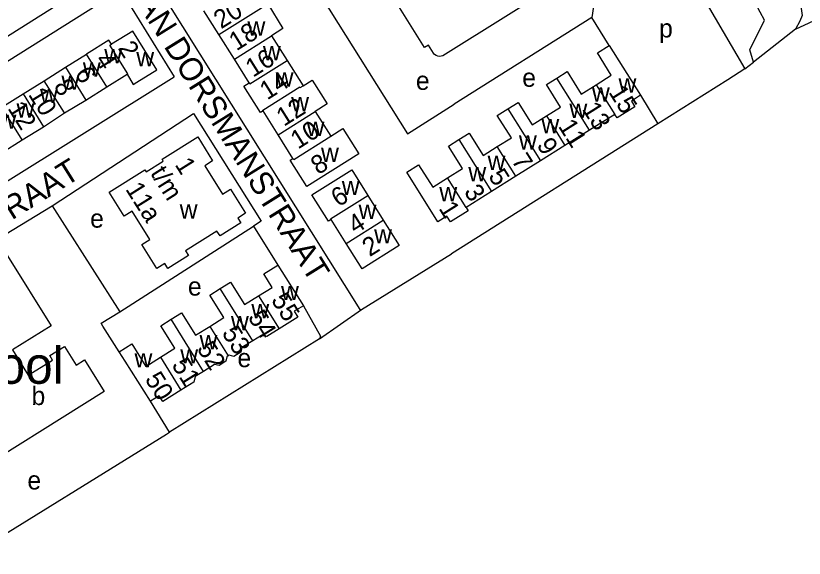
# Model space of a CAD drawing. Extents: x 158848 to 160613, y 385889 to 387762.
# Drawn here: x 159841.7 to 160012.4, y 385996.6 to 386114 of the extents above; entities that cross this region are included whole.
import ezdxf

# ---------------------------------------------------------------- set-up
doc = ezdxf.new("R2010")
doc.units = 0
for name, color, linetype in [('BLT_Basislijn', 7, 'Continuous'), ('BLT_Bebouwing', 7, 'Continuous'), ('BLT_Bebouwing_beschrifting', 7, 'Continuous'), ('BLT_Centroide', 7, 'Continuous'), ('BLT_Huisnummer', 7, 'Continuous'), ('BLT_Huisnummer_ tussenligend', 7, 'Continuous'), ('BLT_Huisnummer_reeks', 7, 'Continuous'), ('BLT_Onderverdeling_panden', 7, 'Continuous'), ('BLT_Straatnaam', 7, 'Continuous'), ('BLT_Vlakafsluiter', 7, 'Continuous')]:
    doc.layers.add(name, color=color, linetype=linetype)

msp = doc.modelspace()

# ---------------------------------------------------------------- linework, layer by layer
at = {"layer": 'BLT_Basislijn'}
for p, q in [((159895.1, 386138.5), (159926.53, 386088.5)), ((159832.6, 386099.65), (159864.36, 386119.63)), ((159864.36, 386119.63), (159876.02, 386100.84)), ((159760.3, 386059.31), (159851.79, 386117.16)), ((159966.41, 386113.66), (159936.62, 386094.87)), ((160010.47, 386111.11), (160001.42, 386104.03)), ((159999.52, 386102.54), (160001.42, 386104.03)), ((159999.52, 386102.54), (159995.82, 386100.15)), ((159762, 386029.78), (159876.02, 386100.84)), ((159995.82, 386100.15), (159980.72, 386090.65)), ((159976.9, 386096.82), (159980.72, 386090.65)), ((159926.53, 386088.5), (159936.62, 386094.87)), ((159849.59, 386072.9), (159880.17, 386092.88)), ((159839.24, 386066.59), (159849.59, 386072.9)), ((159864.25, 386049.96), (159893.14, 386068.51)), ((159893.14, 386068.51), (159898.42, 386060.05)), ((159916.52, 386050.44), (159935.99, 386062.51)), ((159907.48, 386044.07), (159874.99, 386023.85)), ((159874.99, 386023.85), (159870.83, 386030.58))]:
    msp.add_line(p, q, dxfattribs=at)
for points in [[(159974.73, 386128.81), (159966.78, 386116.06), (159966.41, 386113.66)], [(160001.42, 386104.03), (160000.61, 386106.69), (160003.79, 386113.11), (159996.24, 386127.05), (159995.45, 386127.86), (159980.09, 386128.86), (159978.53, 386126.44)], [(159978.53, 386126.44), (159990.11, 386118.68), (159999.52, 386102.54)], [(159871, 386122.61), (159916.2, 386050.47), (159916.52, 386050.44)], [(160009.13, 386122.44), (160011.36, 386118.3), (160011.9, 386114.13), (160011.42, 386112.86), (160010.47, 386111.11)], [(159970.17, 386107.58), (159966.41, 386113.66)], [(159880.17, 386092.88), (159894.8, 386069.57), (159893.14, 386068.51)], [(159980.72, 386090.65), (159935.99, 386062.51)], [(159849.59, 386072.9), (159852.28, 386068.68), (159864.25, 386049.96)], [(159903.96, 386051.26), (159907.64, 386044.65), (159907.48, 386044.07)], [(159864.08, 386041.29), (159860.56, 386046.86), (159860.15, 386047.5), (159864.25, 386049.96)], [(159830.9, 385996.58), (159874.36, 386023.46), (159874.99, 386023.85)]]:
    msp.add_lwpolyline(points, dxfattribs=at)
at = {"layer": 'BLT_Bebouwing'}
for p, q in [((159970.17, 386107.58), (159976.9, 386096.82)), ((159852.49, 386102.88), (159857.02, 386105.71)), ((159900.43, 386104.36), (159903.88, 386098.85)), ((159847.87, 386099.99), (159852.49, 386102.88)), ((159843.29, 386097.14), (159847.87, 386099.99)), ((159861.41, 386098.62), (159865.82, 386101.37)), ((159838.69, 386094.27), (159843.29, 386097.14)), ((159852.24, 386092.99), (159856.85, 386095.78)), ((159906.53, 386093.32), (159909.88, 386087.98)), ((159971.39, 386092.68), (159965.89, 386089.24)), ((159843.09, 386087.2), (159847.71, 386090.02)), ((159965.89, 386089.24), (159960.58, 386085.92)), ((159960.58, 386085.92), (159955.26, 386082.6)), ((159955.26, 386082.6), (159949.96, 386079.29)), ((159949.96, 386079.29), (159944.66, 386075.97)), ((159944.66, 386075.97), (159939.19, 386072.55)), ((159898.42, 386060.05), (159903.96, 386051.26)), ((159865.36, 386039.27), (159864.08, 386041.29)), ((159870.83, 386030.58), (159865.36, 386039.27))]:
    msp.add_line(p, q, dxfattribs=at)
for points in [[(159962.01, 386122.8), (159934.14, 386105.4), (159933.79, 386105.28), (159933.41, 386105.24), (159933.03, 386105.29), (159932.67, 386105.43), (159932.35, 386105.65), (159932.11, 386105.92), (159931.02, 386107.66), (159930.2, 386107.14), (159910.67, 386138.39)], [(159893.73, 386115.05), (159896.25, 386116.64), (159899.54, 386111.29), (159897.08, 386109.71)], [(159885.67, 386109.96), (159882.39, 386115.14)], [(159865.82, 386101.37), (159867.14, 386099.17), (159867.92, 386099.65), (159872.24, 386102.34), (159867.01, 386110.72), (159862.43, 386107.87)], [(159862.43, 386107.87), (159861.87, 386108.73), (159857.02, 386105.71)], [(159889.03, 386104.63), (159885.67, 386109.96)], [(159897.08, 386109.71), (159900.43, 386104.36)], [(159967.35, 386099.12), (159970.61, 386101.16), (159967.63, 386106), (159970.17, 386107.58)], [(159892.25, 386099.52), (159889.03, 386104.63)], [(159958.8, 386100.54), (159961.05, 386101.95), (159964.1, 386097.08), (159967.35, 386099.12)], [(159903.88, 386098.85), (159905.87, 386100.1), (159909.12, 386094.95), (159906.53, 386093.32)], [(159956.55, 386092.34), (159959.61, 386094.26), (159956.55, 386099.14), (159958.8, 386100.54)], [(159856.85, 386095.78), (159861.41, 386098.62)], [(159895.24, 386093.43), (159894.65, 386093.07), (159891.08, 386098.78), (159892.25, 386099.52)], [(159976.9, 386096.82), (159974.97, 386095.58), (159975.74, 386094.35), (159971.86, 386091.93), (159971.39, 386092.68)], [(159948.19, 386093.88), (159950.43, 386095.29), (159953.48, 386090.42), (159956.55, 386092.34)], [(159898.5, 386088.25), (159895.24, 386093.43)], [(159945.94, 386085.7), (159948.99, 386087.61), (159945.94, 386092.47), (159948.19, 386093.88)], [(159847.71, 386090.02), (159852.24, 386092.99)], [(159901.71, 386083.13), (159898.5, 386088.25)], [(159909.88, 386087.98), (159912.48, 386089.62), (159915.95, 386084.13), (159904.68, 386077.06), (159901.11, 386082.76), (159901.71, 386083.13)], [(159937.59, 386087.25), (159939.84, 386088.65), (159942.89, 386083.78), (159945.94, 386085.7)], [(159838.51, 386084.32), (159843.09, 386087.2)], [(159935.18, 386078.93), (159938.41, 386080.96), (159935.35, 386085.84), (159937.59, 386087.25)], [(159939.19, 386072.55), (159939.65, 386071.81), (159935.81, 386069.41), (159935.03, 386070.64), (159933.07, 386069.42), (159926.34, 386080.19), (159928.89, 386081.79), (159931.95, 386076.91), (159935.18, 386078.93)], [(159905.81, 386075.26), (159914.44, 386080.69), (159917.9, 386075.15)], [(159909.97, 386069.92), (159909.39, 386069.55), (159905.81, 386075.26)], [(159917.9, 386075.15), (159921.25, 386069.81)], [(159913.21, 386064.76), (159909.97, 386069.92)], [(159921.25, 386069.81), (159924.71, 386064.28)], [(159924.71, 386064.28), (159916.68, 386059.25), (159913.21, 386064.76)], [(159894.21, 386053.37), (159897.19, 386055.23), (159895.37, 386058.14), (159898.42, 386060.05)], [(159885.94, 386054.97), (159888.18, 386056.38), (159891.23, 386051.5), (159894.21, 386053.37)], [(159883.68, 386046.78), (159886.75, 386048.7), (159883.7, 386053.57), (159885.94, 386054.97)], [(159903.96, 386051.26), (159901.99, 386050.05), (159902.79, 386048.77), (159898.69, 386046.22)], [(159875.32, 386048.32), (159877.56, 386049.73), (159880.61, 386044.85), (159883.68, 386046.78)], [(159873, 386040.09), (159876.12, 386042.04), (159873.07, 386046.92), (159875.32, 386048.32)], [(159898.69, 386046.22), (159896.04, 386044.56), (159894.86, 386044.84), (159893, 386043.68)], [(159893, 386043.68), (159890.62, 386042.2), (159890.42, 386041.22), (159888.9, 386040.29), (159887.91, 386040.53), (159887.68, 386040.38)], [(159864.08, 386041.29), (159866.82, 386043), (159869.87, 386038.13), (159873, 386040.09)], [(159887.68, 386040.38), (159887.42, 386040.21), (159887.2, 386039.22), (159885.71, 386038.29), (159884.71, 386038.52), (159882.36, 386037.05)], [(159882.36, 386037.05), (159880.56, 386035.92), (159880.28, 386034.72), (159877.46, 386032.96)], [(159877.46, 386032.96), (159873.53, 386030.51), (159872.74, 386031.77), (159870.83, 386030.58)]]:
    msp.add_lwpolyline(points, dxfattribs=at)
for points in [[(159861.89, 386075.86), (159869.63, 386080.67), (159869.92, 386080.22), (159873.64, 386082.55), (159873.36, 386083), (159881.08, 386087.82), (159884.32, 386082.62), (159882.63, 386081.56), (159886.47, 386075.41), (159888.16, 386076.48), (159891.41, 386071.27), (159889.76, 386070.24), (159890.42, 386069.19), (159885.91, 386066.37), (159885.25, 386067.42), (159878.41, 386063.16), (159879.08, 386062.1), (159874.63, 386059.32), (159873.97, 386060.37), (159872.27, 386059.31), (159869.02, 386064.5), (159870.71, 386065.58), (159866.88, 386071.73), (159865.17, 386070.67)], [(159811.97, 386044.65), (159839.88, 386062.09), (159849.36, 386046.93), (159840.97, 386041.68), (159844.4, 386036.21), (159849.68, 386039.49), (159849.07, 386040.46), (159852.23, 386042.44), (159854.78, 386038.37), (159856.61, 386039.52), (159860.82, 386032.68), (159829.2, 386012.91), (159824.89, 386019.7), (159827.09, 386021.07), (159824.56, 386025.14), (159827.62, 386027.04), (159828.22, 386026.08), (159835.2, 386030.45), (159831.79, 386035.92), (159821.45, 386029.47)]]:
    msp.add_lwpolyline(points, close=True, dxfattribs=at)
at = {"layer": 'BLT_Onderverdeling_panden'}
for p, q in [((159861.41, 386098.62), (159857.02, 386105.71)), ((159852.49, 386102.88), (159856.85, 386095.78)), ((159852.24, 386092.99), (159847.87, 386099.99)), ((159965.89, 386089.24), (159958.8, 386100.54)), ((159967.35, 386099.12), (159971.39, 386092.68)), ((159843.29, 386097.14), (159847.71, 386090.02)), ((159843.09, 386087.2), (159838.69, 386094.27)), ((159898.5, 386088.25), (159906.53, 386093.32)), ((159948.19, 386093.88), (159955.26, 386082.6)), ((159956.55, 386092.34), (159960.58, 386085.92)), ((159937.59, 386087.25), (159944.66, 386075.97)), ((159949.96, 386079.29), (159945.94, 386085.7)), ((159939.19, 386072.55), (159935.18, 386078.93)), ((159893, 386043.68), (159885.94, 386054.97)), ((159894.21, 386053.37), (159898.69, 386046.22)), ((159882.36, 386037.05), (159875.32, 386048.32)), ((159883.68, 386046.78), (159887.68, 386040.38)), ((159873, 386040.09), (159877.46, 386032.96))]:
    msp.add_line(p, q, dxfattribs=at)
for points in [[(159885.67, 386109.96), (159893.73, 386115.05)], [(159889.03, 386104.63), (159897.08, 386109.71)], [(159865.82, 386101.37), (159865.96, 386101.45), (159862.08, 386107.65), (159862.43, 386107.87)], [(159892.25, 386099.52), (159892.4, 386099.29), (159900.43, 386104.36)], [(159895.24, 386093.43), (159895.15, 386093.58), (159903.18, 386098.65), (159903.29, 386098.48), (159903.88, 386098.85)], [(159901.71, 386083.13), (159901.86, 386082.92), (159909.88, 386087.98)], [(159909.97, 386069.92), (159909.86, 386070.1), (159917.9, 386075.15)], [(159913.21, 386064.76), (159921.25, 386069.81)]]:
    msp.add_lwpolyline(points, dxfattribs=at)
at = {"layer": 'BLT_Vlakafsluiter'}
for p, q in [((160010.47, 386111.11), (160036.39, 386123.3)), ((159907.48, 386044.07), (159916.52, 386050.44))]:
    msp.add_line(p, q, dxfattribs=at)

# ---------------------------------------------------------------- texts
at = {"layer": 'BLT_Bebouwing_beschrifting'}
msp.add_text('School', height=8, dxfattribs=at).set_placement((159819.35, 386034.35))
at = {"layer": 'BLT_Centroide'}
for s, p in [('w', (159891.86, 386109.75)), ('p', (159980.95, 386109.34)), ('w', (159860.86, 386103.75)), ('w', (159895.21, 386104.41)), ('w', (159867.79, 386103.13)), ('w', (159856.22, 386100.88)), ('w', (159897.96, 386098.72)), ('e', (159951.33, 386098.67)), ('w', (159851.58, 386098.01)), ('e', (159928.31, 386098)), ('w', (159972.17, 386097.42)), ('w', (159846.94, 386095.13)), ('w', (159966.42, 386095.47)), ('w', (159841.87, 386092)), ('w', (159901.31, 386093.38)), ('w', (159961.55, 386091.91)), ('w', (159837.97, 386089.58)), ('w', (159955.48, 386088.62)), ('w', (159904.66, 386088.03)), ('w', (159950.62, 386085.05)), ('w', (159907.78, 386082.38)), ('w', (159943.84, 386080.67)), ('w', (159939.67, 386078.19)), ('w', (159912.27, 386075.22)), ('w', (159933.38, 386073.86)), ('w', (159877.19, 386070.13)), ('w', (159915.91, 386070.06)), ('e', (159857.8, 386068.16)), ('w', (159919.27, 386064.75)), ('e', (159878.97, 386053.45)), ('w', (159899.12, 386052.48)), ('w', (159892.69, 386048.56)), ('w', (159888.28, 386045.94)), ('w', (159881.48, 386041.83)), ('w', (159877.31, 386038.77)), ('w', (159867.41, 386037.89)), ('e', (159889.69, 386037.96)), ('b', (159845.11, 386029.75)), ('e', (159844.22, 386011.47))]:
    msp.add_text(s, height=4, dxfattribs=at).set_placement(p)
at = {"layer": 'BLT_Huisnummer'}
for s, rotation, p in [('18', 32.085, (159889.46, 386106.33)), ('2', 302.0052, (159863.7, 386107.05)), ('6', 301.845, (159854.37, 386101.53)), ('14', 32.085, (159896.12, 386095.69)), ('10', 301.845, (159844.3, 386097.01)), ('15', 302.2058, (159969.92, 386097.49)), ('10', 32.085, (159902.79, 386085.05)), ('9', 302.2058, (159954.35, 386086.06)), ('5', 302.2058, (159943.88, 386079.34)), ('6', 32.085, (159911.54, 386072.52)), ('1', 302.2058, (159933.15, 386072.34)), ('2', 32.085, (159918.3, 386061.76)), ('55', 301.9747, (159896.86, 386052.51)), ('52', 301.9747, (159880.79, 386041.98)), ('50', 301.9747, (159869.53, 386035.38))]:
    msp.add_text(s, height=4, rotation=rotation, dxfattribs=at).set_placement(p)
at = {"layer": 'BLT_Huisnummer_ tussenligend'}
for s, rotation, p in [('20', 32.085, (159886.14, 386111.08)), ('16', 32.085, (159893.05, 386100.6)), ('4', 301.845, (159858.74, 386104.53)), ('8', 301.845, (159849.8, 386098.81)), ('12', 301.755, (159839.84, 386094.02)), ('12', 32.085, (159899.73, 386089.97)), ('13', 302.2058, (159964.16, 386093.87)), ('11', 302.2058, (159959, 386090.15)), ('7', 302.2058, (159948.88, 386082.7)), ('8', 32.085, (159907.17, 386079.51)), ('3', 302.2058, (159938.6, 386075.97)), ('4', 32.085, (159915.21, 386066.66)), ('54', 301.9747, (159891.83, 386048.77)), ('53', 301.9747, (159886.19, 386045.37)), ('51', 301.9747, (159875.33, 386038.43))]:
    msp.add_text(s, height=4, rotation=rotation, dxfattribs=at).set_placement(p)
at = {"layer": 'BLT_Huisnummer_reeks'}
for s, p in [('1', (159876.03, 386081.82)), ('t/m', (159870.7, 386079.96)), ('11a', (159865.34, 386076.51))]:
    msp.add_text(s, height=4, rotation=302.1562, dxfattribs=at).set_placement(p)
at = {"layer": 'BLT_Straatnaam'}
for s, rotation, p in [('ADRIAAN DORSMANSTRAAT', 301.8943, (159856.95, 386134.26)), ('PIETER POSTSTRAAT', 31.9493, (159796.08, 386041.8))]:
    msp.add_text(s, height=5, rotation=rotation, dxfattribs=at).set_placement(p)

doc.saveas('drawing.dxf')
